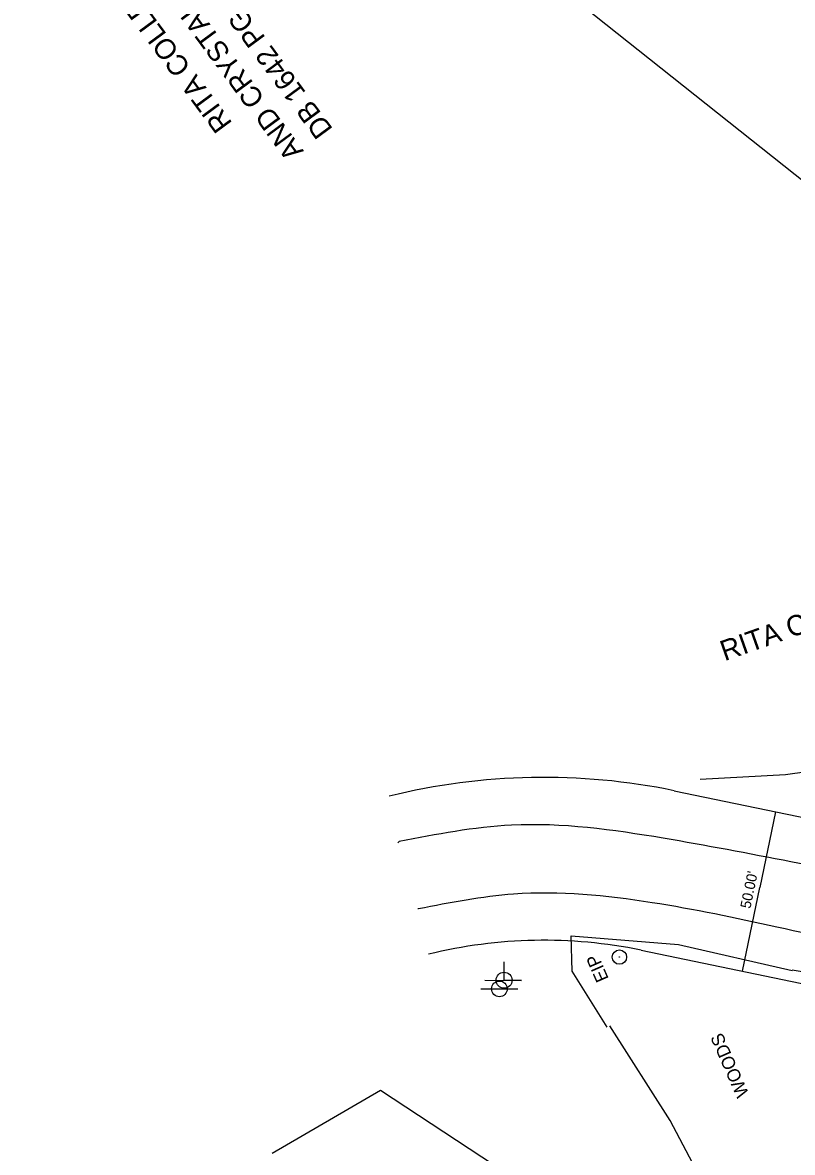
# Model space of a CAD drawing. Extents: x 472260 to 482161, y 489063 to 507124.
# Drawn here: x 474955.3 to 475191.5, y 502110.5 to 502457.3 of the extents above; entities that cross this region are included whole.
import ezdxf

# ---------------------------------------------------------------- set-up
doc = ezdxf.new("R2010")
doc.units = 0
for name, color, linetype in [('Exist Roads EOP Other Cogo Number', 7, 'Continuous'), ('Exist Structure Minor Drop Inlet Cogo Comment', 7, 'Continuous'), ('Exist Structure Minor Drop Inlet Cogo Elevation', 7, 'Continuous'), ('Exist Structure Minor Drop Inlet Cogo Number', 7, 'Continuous'), ('Exist Structure Minor Pipes CMP 15 Inch Cogo Comment', 7, 'Continuous'), ('Prop Drainage Structure Pipe CSP 18in Label', 7, 'Continuous'), ('Prop Drainage Structure Pipe RCP 66in Class III', 7, 'Continuous'), ('Prop Drainage Structure Pipe Stub Out CELL', 7, 'Continuous'), ('Prop Drainage Structure Pipe Welded Steel 66in Label', 7, 'Continuous'), ('Prop Earthen Structure Base Ditch Lateral Detail Label', 7, 'Continuous'), ('Prop Erosion Rip Rap Pad at Outlet Label', 7, 'Continuous'), ('Scratch_Level_7', 7, 'Continuous')]:
    doc.layers.add(name, color=color, linetype=linetype)

# ---------------------------------------------------------------- blocks, each defined once
blk = doc.blocks.new('EXIST PROPERTY IRON PIN')
at = {"layer": 'Exist Structure Minor Drop Inlet Cogo Comment'}
for radius in [0.0441, 0.00141]:
    blk.add_circle((0, 0), radius, dxfattribs=at)
blk = doc.blocks.new('EXIST UTILITIES TELEPHONE POLE')
at = {"layer": 'Prop Drainage Structure Pipe CSP 18in Label'}
for p, q in [((-0.1135, 0), (0.11325, 0)), ((0, 0), (0, 0))]:
    blk.add_line(p, q, dxfattribs=at)
blk.add_circle((0, 0), 0.04813, dxfattribs=at)
blk = doc.blocks.new('EXIST UTILITIES POWER JOINT USE TELEPHONE')
at = {"layer": 'Prop Earthen Structure Base Ditch Lateral Detail Label'}
blk.add_line((0, 0), (0, 0), dxfattribs=at)
blk.add_lwpolyline([(-0.1188, 0), (0.108, -0.0008), (0, -0.0004), (0, 0.1125)], dxfattribs=at)
blk.add_circle((0, 0.0001), 0.049, dxfattribs=at)

msp = doc.modelspace()

# ---------------------------------------------------------------- linework, layer by layer
at = {"layer": 'Exist Structure Minor Drop Inlet Cogo Elevation'}
for p, q in [((475155.2, 502221.53), (475238.44, 502204.31)), ((475145.07, 502172.57), (475228.32, 502155.35))]:
    msp.add_line(p, q, dxfattribs=at)
for radius in [197.32, 147.32]:
    msp.add_arc((475115.23, 502028.3), radius, 78.3142, 103.9027, dxfattribs=at)
at = {"layer": 'Exist Structure Minor Drop Inlet Cogo Number'}
msp.add_line((475436.14, 502216.61), (474955.3, 502599.14), dxfattribs=at)
at = {"layer": 'Exist Structure Minor Pipes CMP 15 Inch Cogo Comment'}
for p in [(475186.35, 502215.09), (475176.22, 502166.13)]:
    msp.add_line(p, (475181.54, 502191.85), dxfattribs=at)
at = {"layer": 'Prop Drainage Structure Pipe Stub Out CELL'}
for p, q in [((475070.83, 502205.92), (475070.44, 502205.5)), ((475076.82, 502185.23), (475076.59, 502185.24))]:
    msp.add_line(p, q, dxfattribs=at)
for points in [[(475268.62, 502179.94), (475233.46, 502190.46), (475191.08, 502199.68), (475151.86, 502206.94), (475105.34, 502210.94), (475070.83, 502205.92)], [(475257.79, 502158.82), (475257.44, 502159.1), (475227.15, 502170.48), (475186.73, 502179.65), (475148.45, 502187.15), (475105.98, 502189.78), (475076.82, 502185.23)]]:
    msp.add_spline(points, degree=3, dxfattribs=at)
at = {"layer": 'Prop Erosion Rip Rap Pad at Outlet Label'}
for points in [[(475163.17, 502225.11), (475189.43, 502226.55), (475238.82, 502233.5), (475274.68, 502246.45), (475301.03, 502246.88)], [(475134.72, 502148.92), (475123.9, 502166.13), (475123.58, 502176.97), (475156.55, 502174.28), (475191.47, 502166.29)], [(475191.46, 502166.53), (475203.55, 502164.53), (475233.17, 502157.83), (475250.47, 502150.89)], [(475166.86, 502095.85), (475154.01, 502120.27), (475135.48, 502149.35)], [(475031.83, 502110.25), (475065.08, 502129.6), (475111.79, 502098.93), (475123.75, 502067.92), (475128.5, 502030.49), (475138.21, 501995.51), (475148.65, 501978.89), (475162.17, 501976.93), (475179.77, 501987.23), (475160.61, 501954.87), (475137.8, 501920.75), (475118.95, 501897.09)]]:
    msp.add_lwpolyline(points, dxfattribs=at)

# ---------------------------------------------------------------- block references
at = {"layer": 'Exist Structure Minor Drop Inlet Cogo Comment', "xscale": 50, "yscale": 50}
msp.add_blockref('EXIST PROPERTY IRON PIN', (475138.43, 502170.45), dxfattribs=at)
at = {"layer": 'Prop Drainage Structure Pipe CSP 18in Label', "xscale": 50, "yscale": 50}
msp.add_blockref('EXIST UTILITIES TELEPHONE POLE', (475101.6, 502160.7), dxfattribs=at)
at = {"layer": 'Prop Earthen Structure Base Ditch Lateral Detail Label', "xscale": 50, "yscale": 50}
msp.add_blockref('EXIST UTILITIES POWER JOINT USE TELEPHONE', (475103.03, 502163.34), dxfattribs=at)

# ---------------------------------------------------------------- texts
at = {"layer": 'Exist Roads EOP Other Cogo Number'}
msp.add_text('EIP', height=4, rotation=113.6764, dxfattribs=at).set_placement((475135.22, 502163.84))
at = {"layer": 'Exist Structure Minor Pipes CMP 15 Inch Cogo Comment'}
msp.add_text("50.00'", height=3.2, rotation=78.3142, dxfattribs=at).set_placement((475178.6, 502185.15))
at = {"layer": 'Prop Drainage Structure Pipe RCP 66in Class III'}
msp.add_text('WOODS', height=4, rotation=113.6764, dxfattribs=at).set_placement((475178.26, 502128.44))
at = {"layer": 'Prop Drainage Structure Pipe Welded Steel 66in Label'}
msp.add_text('DB 1642 PG 341', height=6.25, rotation=126.4463, dxfattribs=at).set_placement((475050.7, 502424.63))
at = {"layer": 'Scratch_Level_7'}
for s, rotation, p in [('AND CRYSTAL KELLY ROGERS', 126.4463, (475041.7, 502417.88)), ('RITA COLLEEN KELLY', 126.4463, (475019.83, 502426.45)), ('RITA COLLEEN KELLY ', 19.423, (475170.71, 502261.26))]:
    msp.add_text(s, height=6.25, rotation=rotation, dxfattribs=at).set_placement(p)

doc.saveas('drawing.dxf')
